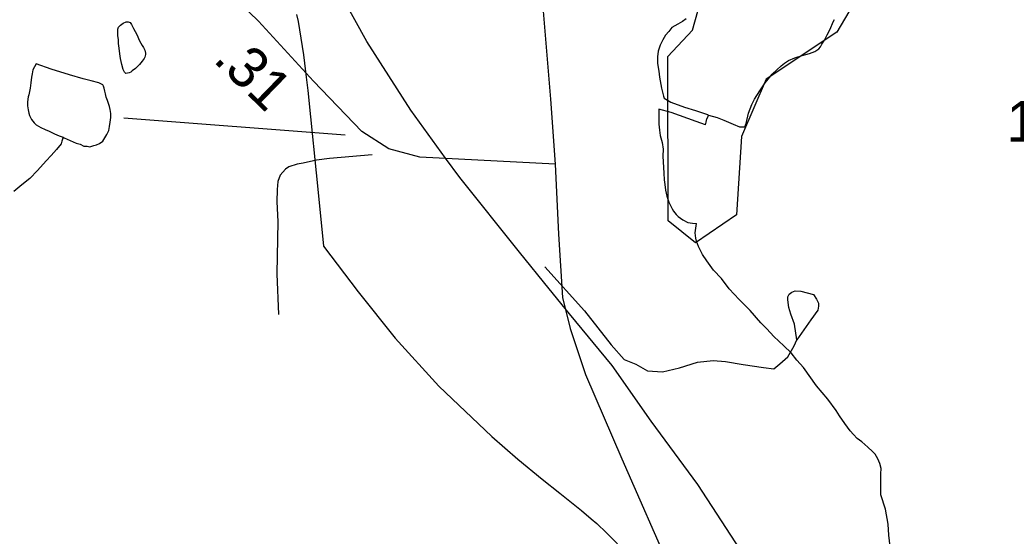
# Model space of a CAD drawing. Extents: x 2001466 to 2224147, y 644118 to 847247.
# Drawn here: x 2046028 to 2049070, y 673718 to 675296 of the extents above; entities that cross this region are included whole.
import ezdxf

# ---------------------------------------------------------------- set-up
doc = ezdxf.new("R2010")
doc.units = 0
for name, color, linetype in [('Exist Hydrographic Misc Water Feature', 7, 'Continuous'), ('Exist Railroad Mainline', 7, 'Continuous'), ('Exist Road Non-System Type 51', 7, 'Continuous'), ('Exist Road Secondary Mileage Hundredths English Label', 7, 'Continuous'), ('Exist Road Secondary Type 51 Attributed', 7, 'Continuous'), ('Exist Road Secondary Type 51 Number Label', 7, 'Continuous')]:
    doc.layers.add(name, color=color, linetype=linetype)

msp = doc.modelspace()

# ---------------------------------------------------------------- linework, layer by layer
at = {"layer": 'Exist Hydrographic Misc Water Feature'}
msp.add_line((2046873, 675313.1), (2046877.7, 675291.8), dxfattribs=at)
for points in [[(2048572.6, 675342.9), (2048522.6, 675258.7), (2048306.7, 675115.4), (2048231.6, 674939.7), (2048215.6, 674700.6), (2048090.6, 674614.6), (2048007.5, 674681.9), (2048006.7, 675183.9), (2048081.5, 675264.4), (2048114.5, 675381.8)], [(2046393.1, 675232.2), (2046401.3, 675218.2), (2046405.2, 675212.2), (2046409.3, 675204.2), (2046411.2, 675194.2), (2046411.2, 675190.2), (2046409.3, 675182.2), (2046407.3, 675178.2), (2046401.3, 675170.2), (2046393.3, 675160.1), (2046385.3, 675152.1), (2046381.4, 675148.1), (2046371.4, 675140.1), (2046367.3, 675136.1), (2046361.4, 675134.1), (2046351.3, 675132.1), (2046347.4, 675136.1), (2046343.3, 675144.1), (2046339.4, 675160.1), (2046335.3, 675178), (2046333.3, 675192), (2046331.2, 675210), (2046329.2, 675224), (2046329.2, 675236), (2046327.1, 675248), (2046327.1, 675254), (2046327.1, 675260), (2046327.1, 675268), (2046329.2, 675274), (2046335.1, 675280), (2046343.1, 675286), (2046353.1, 675290.1), (2046359.1, 675290.1), (2046365, 675288.1), (2046369.1, 675282.1), (2046375.1, 675270.1), (2046385.1, 675252.1), (2046393.1, 675232.2)], [(2046877.7, 675291.8), (2046893.7, 675189.8), (2046902.5, 675121.6)], [(2046877.7, 675291.8), (2046893.7, 675189.8), (2046902.5, 675121.6)], [(2048062.7, 675299.1), (2048050.8, 675291.2), (2048036.6, 675283.2), (2048018.8, 675273.3), (2048009.2, 675261), (2047999.1, 675249.1), (2047990.7, 675235), (2047983.1, 675219.1), (2047977, 675201), (2047974.9, 675183), (2047974.9, 675163.2), (2047979, 675139), (2047981.3, 675121.3), (2047985.2, 675099.2), (2047987, 675087.1), (2047993.2, 675063), (2047995.2, 675057.1), (2048015.3, 675045.1), (2048057.3, 675029.4), (2048091.2, 675019.4), (2048127.1, 675007.5), (2048131, 675005.3)], [(2048131, 675005.3), (2048157.4, 674997.6), (2048177.3, 674989.7), (2048205.4, 674977.7), (2048225.3, 674969.4), (2048241.1, 674969.5), (2048245.4, 674979.8), (2048253.2, 675011.5), (2048263, 675037.6), (2048270.8, 675053.8), (2048287, 675079.7), (2048303.4, 675103.6), (2048313, 675115.5), (2048324.7, 675130), (2048338.9, 675143.7), (2048352.8, 675155.7), (2048363.1, 675163.9), (2048375.2, 675171.8), (2048394.6, 675179.8), (2048416.8, 675187.8), (2048438.7, 675193.8), (2048454.9, 675199.9), (2048467, 675207.8), (2048472.6, 675213.9), (2048477.1, 675222.1), (2048484.5, 675233.9), (2048492.7, 675250.1), (2048502.5, 675268.1), (2048510.9, 675290), (2048514.8, 675297.9)], [(2046159.8, 674937.7), (2046163.7, 674935.8), (2046199.8, 674919.9), (2046211.7, 674915.9), (2046223.8, 674909.9), (2046233.8, 674909.9), (2046241.8, 674907.9), (2046253.7, 674912), (2046261.7, 674914), (2046271.7, 674918), (2046281.8, 674926), (2046287.7, 674936), (2046293.7, 674946), (2046299.8, 674958), (2046301.7, 674970), (2046303.5, 674984), (2046305.6, 674998), (2046305.6, 675010), (2046303.5, 675022), (2046301.7, 675032), (2046297.6, 675044), (2046295.5, 675050), (2046291.4, 675060), (2046289.6, 675070), (2046287.5, 675078), (2046285.5, 675088), (2046283.4, 675093.9), (2046281.6, 675097.9), (2046277.5, 675099.9), (2046269.3, 675103.9), (2046245.3, 675109.9), (2046221.3, 675115.8), (2046179.5, 675127.8), (2046123.3, 675145.6), (2046077.4, 675161.6), (2046067.3, 675143.6), (2046065.5, 675131.6), (2046063.4, 675121.6), (2046061.6, 675103.6), (2046059.5, 675087.6), (2046055.4, 675067.5), (2046053.6, 675061.5), (2046051.5, 675045.5), (2046051.5, 675033.5), (2046053.6, 675021.6), (2046055.6, 675011.6), (2046057.7, 675003.6), (2046063.6, 674991.6), (2046071.8, 674981.6), (2046077.8, 674975.6), (2046091.7, 674967.6), (2046105.7, 674961.6), (2046117.7, 674955.7), (2046133.7, 674947.7), (2046147.7, 674941.7), (2046159.8, 674937.7)], [(2046902.5, 675121.6), (2046907.6, 675080.9), (2046941, 674748.2)], [(2046902.5, 675121.6), (2046907.6, 675080.9), (2046941, 674748.2)], [(2048121.3, 674975.5), (2048093.2, 674985.4), (2048017.1, 675013.2), (2047979.2, 675023), (2047979.2, 674977.2), (2047981.3, 674959), (2047983.3, 674943.3), (2047989.5, 674921.2), (2047991.7, 674901), (2047991.3, 674879.2), (2047993.8, 674827.3), (2047995.6, 674807.2), (2047997.5, 674793.1), (2047999.5, 674775.3), (2048003.8, 674757.3), (2048009.8, 674739.3), (2048020, 674719.1), (2048023.7, 674711.2), (2048031.9, 674701.5), (2048037.7, 674695.3), (2048051.8, 674685.5), (2048067.8, 674677.4), (2048081.5, 674675.3), (2048094, 674673.4)], [(2048121.3, 674975.5), (2048123.6, 674983.3), (2048125.2, 674993.5), (2048129.5, 675001.4), (2048131, 675005.3)], [(2046159.8, 674937.7), (2046155.7, 674925.8), (2046153.8, 674917.8), (2046139.9, 674899.7), (2046123.9, 674881.7), (2046107.9, 674865.7), (2046082.1, 674835.6), (2046058.1, 674811.6), (2046034.1, 674791.6), (2046010.1, 674771.5)], [(2046941, 674748.2), (2046955.6, 674604.3), (2047060.6, 674464.8), (2047174.4, 674323.3), (2047307.7, 674176.5)], [(2048657.1, 673844.6), (2048657.1, 673854.7), (2048657.1, 673864.4), (2048657.1, 673890.8), (2048657.1, 673908.6), (2048657.3, 673924.4), (2048653.2, 673940.5), (2048647.1, 673954.8), (2048639.1, 673968.6), (2048631.1, 673976.7), (2048617.3, 673990.5), (2048599.1, 674006.2), (2048584.9, 674016.5), (2048573, 674028.4), (2048563.2, 674040.5), (2048547.2, 674062.4), (2048530.8, 674086.4), (2048520.8, 674102.5), (2048494.9, 674136.4), (2048460.7, 674178.1), (2048420.7, 674234.1), (2048400.6, 674256.2), (2048382.6, 674278), (2048360.2, 674300), (2048330.5, 674328.1), (2048308.5, 674351.7), (2048290.3, 674369.9), (2048258.3, 674407.5), (2048224, 674441.5), (2048194.1, 674473.7), (2048170.1, 674505.7), (2048145.9, 674531.6), (2048126, 674559.4), (2048112.3, 674579.4), (2048100.2, 674603.5), (2048093.8, 674619.5), (2048092.2, 674629.5), (2048090.1, 674645.2), (2048091.6, 674659.5), (2048094, 674673.4)], [(2047307.7, 674176.5), (2047468.6, 674022.6), (2047548.6, 673953.9), (2047622.8, 673892.3), (2047676.8, 673849.2)], [(2047307.7, 674176.5), (2047468.6, 674022.6), (2047548.6, 673953.9), (2047622.8, 673892.3), (2047676.8, 673849.2)], [(2047676.8, 673849.2), (2047742.6, 673796.8), (2047772.1, 673771.4)], [(2047676.8, 673849.2), (2047742.6, 673796.8), (2047772.1, 673771.4)], [(2048685.6, 673686.9), (2048681.5, 673720.8), (2048679.5, 673754.8), (2048671.5, 673800.6), (2048657.1, 673844.6)], [(2047772.1, 673771.4), (2047789.5, 673756.3), (2047818.7, 673727.8)], [(2047772.1, 673771.4), (2047789.5, 673756.3), (2047818.7, 673727.8)], [(2047818.7, 673727.8), (2047844.5, 673702.5), (2047900.5, 673642.7), (2047952.6, 673582.9), (2048056.5, 673450.8), (2048063.7, 673442)], [(2047818.7, 673727.8), (2047844.5, 673702.5), (2047900.5, 673642.7), (2047952.6, 673582.9), (2048056.5, 673450.8), (2048063.7, 673442)]]:
    msp.add_lwpolyline(points, dxfattribs=at)
at = {"layer": 'Exist Railroad Mainline'}
for points in [[(2047327.9, 674874), (2047221.5, 675019.8), (2047087.4, 675229.7), (2046987.3, 675411.8), (2046917.3, 675571.8), (2046879.1, 675775.8), (2046839, 676027.8), (2046823.8, 676143.3), (2046806.8, 676271.8), (2046768.8, 676576), (2046732.5, 676936), (2046686.3, 677280.1), (2046654.1, 677554.2), (2046646.1, 677674.1), (2046649.6, 677864.9), (2046683.6, 678023.6), (2046717.6, 678148.3), (2046774.2, 678288.1), (2046815.8, 678420.3), (2046838.4, 678560.1), (2046881, 679318.8), (2046890.6, 680593)], [(2047644.1, 674474.3), (2047553.9, 674585.9), (2047371.7, 674814), (2047327.9, 674874)], [(2049760.1, 672513.6), (2049542.8, 672563.4), (2049328.5, 672623.6), (2049327.5, 672623.9), (2049110.7, 672690.4), (2048974.7, 672760.4), (2048832.7, 672856.3), (2048706.5, 672968.2), (2048582.5, 673134.4), (2048434.3, 673360.2), (2048242.3, 673654.1), (2048098.2, 673876.2), (2047956, 674070.1), (2047836, 674240.1), (2047705.8, 674398), (2047644.1, 674474.3)]]:
    msp.add_lwpolyline(points, dxfattribs=at)
at = {"layer": 'Exist Road Non-System Type 51'}
msp.add_line((2047020.9, 674943.9), (2046346, 674995.6), dxfattribs=at)
for points in [[(2047103.7, 674884.2), (2046973.5, 674872.8), (2046933.4, 674867.7), (2046893.2, 674858.5), (2046875.1, 674854.8), (2046849, 674847.4), (2046838.8, 674839.6), (2046822.5, 674821.9), (2046816.1, 674802), (2046813.6, 674778.1), (2046812.8, 674740.1), (2046815.6, 674680.1), (2046812.3, 674520.1), (2046817.8, 674396)], [(2047630.8, 674541.5), (2047752, 674407), (2047833.9, 674303.4), (2047873, 674258.6), (2047908.7, 674243.9), (2047944.3, 674223.1), (2047990.2, 674220.2), (2048042.5, 674233.1), (2048096.8, 674250), (2048144.9, 674255.1), (2048182.9, 674252.3), (2048236.7, 674243.2), (2048298.5, 674233.9), (2048330.4, 674229.3), (2048348.7, 674244.9), (2048373.2, 674266.4), (2048391.8, 674300), (2048400.2, 674317.9)], [(2048400.2, 674317.9), (2048393.2, 674366), (2048381.8, 674396.2), (2048376.2, 674417.4), (2048372.7, 674440.4), (2048373, 674449.6), (2048377.1, 674458.3), (2048385.1, 674464.4), (2048395.3, 674468), (2048412, 674467.2), (2048431.6, 674462.1), (2048451, 674456.8), (2048460.7, 674442.6), (2048466.5, 674430.5), (2048466.9, 674420.7), (2048464, 674408.6), (2048443.4, 674379), (2048400.2, 674317.9)]]:
    msp.add_lwpolyline(points, dxfattribs=at)
at = {"layer": 'Exist Road Secondary Type 51 Attributed'}
for points in [[(2047544.9, 676378.5), (2047576.5, 676139.8), (2047596.1, 675737.4), (2047625.1, 675334.9), (2047648.3, 675053.9), (2047662, 674855.3)], [(2047662, 674855.3), (2047249.3, 674876.5), (2047154.3, 674901.8), (2047072, 674954.7), (2046924.2, 675108.9), (2046756.3, 675292.7), (2046617, 675427.9), (2046513.6, 675501.8), (2046285.7, 675626)], [(2047662, 674855.3), (2047673.1, 674640.9), (2047684.7, 674447.6), (2047707.9, 674352.5), (2047754.9, 674212), (2047865.8, 673954.3), (2048019.3, 673603.6), (2048170.3, 673283.5), (2048256.9, 673084.9), (2048314.4, 672928.6), (2048350.3, 672770.2), (2048379.8, 672632.8), (2048412.1, 672478.6)]]:
    msp.add_lwpolyline(points, dxfattribs=at)

# ---------------------------------------------------------------- texts
at = {"layer": 'Exist Road Secondary Mileage Hundredths English Label'}
msp.add_text('.31', height=125, rotation=315.8618, dxfattribs=at).set_placement((2046615.1, 675171.4))
at = {"layer": 'Exist Road Secondary Type 51 Number Label'}
msp.add_text('1259', height=125, dxfattribs=at).set_placement((2049040.9, 674923.5))

doc.saveas('drawing.dxf')
